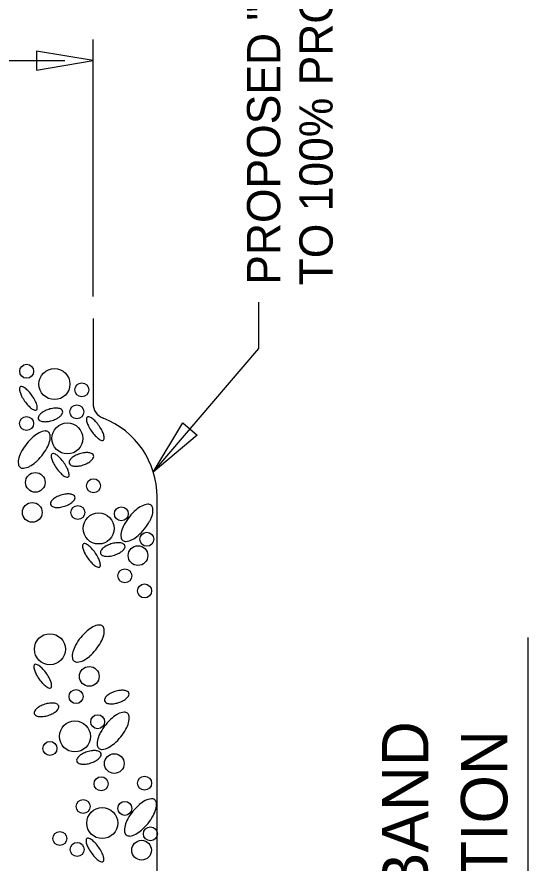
# Model space of a CAD drawing. Extents: x 0 to 8.5, y 0 to 11.
# Drawn here: x 5.35 to 6.273, y 8.342 to 9.87 of the extents above; entities that cross this region are included whole.
import ezdxf

# ---------------------------------------------------------------- set-up
doc = ezdxf.new("R2010")
doc.units = 0
for name, color, linetype in [('DTL-GRAVEL', 7, 'Continuous'), ('DTL-TEXT', 7, 'Continuous'), ('Old_Level_11', 7, 'Continuous')]:
    doc.layers.add(name, color=color, linetype=linetype)

msp = doc.modelspace()

# ---------------------------------------------------------------- linework, layer by layer
at = {"layer": 'DTL-GRAVEL'}
for centre, radius in [((5.3671, 9.2304), 0.0126), ((5.4174, 9.2073), 0.028), ((5.4669, 9.1968), 0.0126), ((5.4579, 9.1571), 0.0126), ((5.367, 9.1361), 0.0126), ((5.4407, 9.1092), 0.028), ((5.3828, 9.0298), 0.0178), ((5.4878, 9.0237), 0.0126), ((5.3773, 8.9756), 0.0178), ((5.4596, 8.9753), 0.0126), ((5.4972, 8.9465), 0.028), ((5.5382, 8.973), 0.0126), ((5.5844, 8.927), 0.0126), ((5.5683, 8.8975), 0.0178), ((5.5444, 8.861), 0.0126), ((5.5802, 8.8337), 0.0126), ((5.4092, 8.7284), 0.028), ((5.4803, 8.6794), 0.0178), ((5.4564, 8.6429), 0.0126), ((5.4954, 8.5975), 0.0126), ((5.4544, 8.5709), 0.028), ((5.4092, 8.5493), 0.0126), ((5.5255, 8.522), 0.0178), ((5.5016, 8.4855), 0.0126), ((5.5802, 8.4865), 0.0126), ((5.4692, 8.4443), 0.0126), ((5.5446, 8.441), 0.0126), ((5.5036, 8.4145), 0.028), ((5.5907, 8.395), 0.0126), ((5.4272, 8.3866), 0.0126), ((5.4585, 8.3669), 0.0126), ((5.5747, 8.3655), 0.0178)]:
    msp.add_circle(centre, radius, dxfattribs=at)
for centre, radius, start, end in [((5.3744, 9.1988), 0.0203, 176.964, 197.0838), ((5.3574, 9.1997), 0.00323, 125.0965, 176.964), ((5.3574, 9.1997), 0.00323, 73.2289, 125.0965), ((5.3525, 9.1834), 0.0203, 53.1091, 73.2289), ((5.3964, 9.2056), 0.0432, 197.0838, 207.4256), ((5.4277, 9.2218), 0.0785, 207.4256, 215.0965), ((5.3387, 9.1651), 0.0432, 42.7673, 53.1091), ((5.3128, 9.1411), 0.0785, 35.0965, 42.7673), ((5.3128, 9.1411), 0.0785, 27.4256, 35.0965), ((5.4277, 9.2218), 0.0785, 215.0965, 222.7673), ((5.3441, 9.1574), 0.0432, 17.0838, 27.4256), ((5.366, 9.1641), 0.0203, 356.964, 17.0838), ((5.4018, 9.1979), 0.0432, 222.7673, 233.1091), ((5.388, 9.1795), 0.0203, 233.1091, 253.2289), ((5.3831, 9.1632), 0.00323, 253.2289, 305.0965), ((5.3831, 9.1632), 0.00323, 305.0965, 356.964), ((5.4127, 9.1313), 0.0304, 118.2722, 132.0822), ((5.4223, 9.1134), 0.0506, 107.5826, 118.2722), ((5.4223, 9.1134), 0.0506, 96.893, 107.5826), ((5.4198, 9.1335), 0.0304, 83.0831, 96.893), ((5.4215, 9.1471), 0.0167, 59.8512, 83.0831), ((5.4168, 9.1618), 0.0167, 312.0822, 335.3141), ((5.4272, 9.1571), 0.0052, 17.5826, 59.8512), ((5.4272, 9.1571), 0.0052, 335.3141, 17.5826), ((5.3931, 9.1462), 0.0052, 155.3141, 197.5826), ((5.3931, 9.1462), 0.0052, 197.5826, 239.8512), ((5.4035, 9.1414), 0.0167, 132.0822, 155.3141), ((5.3988, 9.1561), 0.0167, 239.8512, 263.0831), ((5.4005, 9.1698), 0.0304, 263.0831, 276.893), ((5.398, 9.1898), 0.0506, 276.893, 287.5826), ((5.398, 9.1898), 0.0506, 287.5826, 298.2722), ((5.4076, 9.172), 0.0304, 298.2722, 312.0822), ((5.4784, 9.1452), 0.00323, 125.0965, 176.964), ((5.4954, 9.1443), 0.0203, 176.964, 197.0838), ((5.4784, 9.1452), 0.00323, 73.2289, 125.0965), ((5.4735, 9.1289), 0.0203, 53.1091, 73.2289), ((5.4597, 9.1105), 0.0432, 42.7673, 53.1091), ((5.4338, 9.0866), 0.0785, 35.0965, 42.7673), ((5.5173, 9.151), 0.0432, 197.0838, 207.4256), ((5.5486, 9.1673), 0.0785, 207.4256, 215.0965), ((5.4338, 9.0866), 0.0785, 27.4256, 35.0965), ((5.4412, 9.0401), 0.0951, 130.9175, 140.9829), ((5.4156, 9.0697), 0.056, 117.7861, 130.9175), ((5.4033, 9.093), 0.0297, 95.0094, 117.7861), ((5.4014, 9.1143), 0.00824, 50.9829, 95.0094), ((5.4014, 9.1143), 0.00824, 6.9564, 50.9829), ((5.3801, 9.1117), 0.0297, 344.1797, 6.9564), ((5.5486, 9.1673), 0.0785, 215.0965, 222.7673), ((5.5228, 9.1433), 0.0432, 222.7673, 233.1091), ((5.509, 9.125), 0.0203, 233.1091, 253.2289), ((5.4651, 9.1028), 0.0432, 17.0838, 27.4256), ((5.504, 9.1087), 0.00323, 305.0965, 356.964), ((5.487, 9.1096), 0.0203, 356.964, 17.0838), ((5.4412, 9.0401), 0.0951, 140.9829, 151.0483), ((5.3548, 9.1189), 0.056, 331.0483, 344.1797), ((5.504, 9.1087), 0.00323, 253.2289, 305.0965), ((5.4069, 9.0591), 0.056, 151.0483, 164.1797), ((5.3206, 9.1378), 0.0951, 310.9175, 320.9829), ((5.3206, 9.1378), 0.0951, 320.9829, 331.0483), ((5.4318, 9.0779), 0.0203, 176.964, 197.0838), ((5.4148, 9.0788), 0.00323, 125.0965, 176.964), ((5.4148, 9.0788), 0.00323, 73.2289, 125.0965), ((5.4099, 9.0624), 0.0203, 53.1091, 73.2289), ((5.3961, 9.0441), 0.0432, 42.7673, 53.1091), ((5.4685, 9.0508), 0.0304, 118.2722, 132.0822), ((5.4781, 9.033), 0.0506, 107.5826, 118.2722), ((5.4781, 9.033), 0.0506, 96.893, 107.5826), ((5.4757, 9.0531), 0.0304, 83.0831, 96.893), ((5.4773, 9.0667), 0.0167, 59.8512, 83.0831), ((5.4831, 9.0766), 0.0052, 17.5826, 59.8512), ((5.4831, 9.0766), 0.0052, 335.3141, 17.5826), ((5.3816, 9.0662), 0.0297, 164.1797, 186.9564), ((5.3604, 9.0636), 0.00824, 186.9564, 230.9829), ((5.3462, 9.1083), 0.056, 297.7861, 310.9175), ((5.4538, 9.0846), 0.0432, 197.0838, 207.4256), ((5.4851, 9.1008), 0.0785, 207.4256, 215.0965), ((5.3702, 9.0201), 0.0785, 35.0965, 42.7673), ((5.3702, 9.0201), 0.0785, 27.4256, 35.0965), ((5.4489, 9.0658), 0.0052, 155.3141, 197.5826), ((5.4489, 9.0658), 0.0052, 197.5826, 239.8512), ((5.4593, 9.061), 0.0167, 132.0822, 155.3141), ((5.4539, 9.1094), 0.0506, 287.5826, 298.2722), ((5.4635, 9.0916), 0.0304, 298.2722, 312.0822), ((5.4726, 9.0814), 0.0167, 312.0822, 335.3141), ((5.3604, 9.0636), 0.00824, 230.9829, 275.0094), ((5.3585, 9.085), 0.0297, 275.0094, 297.7861), ((5.4851, 9.1008), 0.0785, 215.0965, 222.7673), ((5.4592, 9.0769), 0.0432, 222.7673, 233.1091), ((5.4015, 9.0364), 0.0432, 17.0838, 27.4256), ((5.4234, 9.0431), 0.0203, 356.964, 17.0838), ((5.4546, 9.0757), 0.0167, 239.8512, 263.0831), ((5.4563, 9.0893), 0.0304, 263.0831, 276.893), ((5.4539, 9.1094), 0.0506, 276.893, 287.5826), ((5.4454, 9.0585), 0.0203, 233.1091, 253.2289), ((5.4405, 9.0422), 0.00323, 253.2289, 305.0965), ((5.4405, 9.0422), 0.00323, 305.0965, 356.964), ((5.4348, 8.9763), 0.0304, 118.2722, 132.0822), ((5.4444, 8.9585), 0.0506, 107.5826, 118.2722), ((5.4444, 8.9585), 0.0506, 96.893, 107.5826), ((5.4419, 8.9786), 0.0304, 83.0831, 96.893), ((5.4436, 8.9922), 0.0167, 59.8512, 83.0831), ((5.4493, 9.0021), 0.0052, 17.5826, 59.8512), ((5.4493, 9.0021), 0.0052, 335.3141, 17.5826), ((5.4152, 8.9913), 0.0052, 155.3141, 197.5826), ((5.4152, 8.9913), 0.0052, 197.5826, 239.8512), ((5.4256, 8.9865), 0.0167, 132.0822, 155.3141), ((5.4209, 9.0012), 0.0167, 239.8512, 263.0831), ((5.4202, 9.0349), 0.0506, 276.893, 287.5826), ((5.4202, 9.0349), 0.0506, 287.5826, 298.2722), ((5.4297, 9.0171), 0.0304, 298.2722, 312.0822), ((5.4389, 9.0069), 0.0167, 312.0822, 335.3141), ((5.6011, 8.9374), 0.056, 117.7861, 130.9175), ((5.5888, 8.9607), 0.0297, 95.0094, 117.7861), ((5.5869, 8.9821), 0.00824, 50.9829, 95.0094), ((5.5869, 8.9821), 0.00824, 6.9564, 50.9829), ((5.4226, 9.0148), 0.0304, 263.0831, 276.893), ((5.6267, 8.9079), 0.0951, 130.9175, 140.9829), ((5.5404, 8.9866), 0.056, 331.0483, 344.1797), ((5.5657, 8.9795), 0.0297, 344.1797, 6.9564), ((5.6267, 8.9079), 0.0951, 140.9829, 151.0483), ((5.5061, 9.0056), 0.0951, 320.9829, 331.0483), ((5.5672, 8.934), 0.0297, 164.1797, 186.9564), ((5.5925, 8.9268), 0.056, 151.0483, 164.1797), ((5.5061, 9.0056), 0.0951, 310.9175, 320.9829), ((5.5459, 8.9314), 0.00824, 186.9564, 230.9829), ((5.5459, 8.9314), 0.00824, 230.9829, 275.0094), ((5.544, 8.9527), 0.0297, 275.0094, 297.7861), ((5.5317, 8.976), 0.056, 297.7861, 310.9175), ((5.4714, 8.9161), 0.00323, 125.0965, 176.964), ((5.4884, 8.9152), 0.0203, 176.964, 197.0838), ((5.4714, 8.9161), 0.00323, 73.2289, 125.0965), ((5.4665, 8.8997), 0.0203, 53.1091, 73.2289), ((5.4527, 8.8814), 0.0432, 42.7673, 53.1091), ((5.4268, 8.8574), 0.0785, 35.0965, 42.7673), ((5.5159, 8.8983), 0.0167, 132.0822, 155.3141), ((5.5251, 8.8881), 0.0304, 118.2722, 132.0822), ((5.5347, 8.8703), 0.0506, 107.5826, 118.2722), ((5.5347, 8.8703), 0.0506, 96.893, 107.5826), ((5.5322, 8.8904), 0.0304, 83.0831, 96.893), ((5.5339, 8.904), 0.0167, 59.8512, 83.0831), ((5.5292, 8.9187), 0.0167, 312.0822, 335.3141), ((5.5397, 8.9139), 0.0052, 17.5826, 59.8512), ((5.5397, 8.9139), 0.0052, 335.3141, 17.5826), ((5.5103, 8.9219), 0.0432, 197.0838, 207.4256), ((5.5416, 8.9381), 0.0785, 207.4256, 215.0965), ((5.4268, 8.8574), 0.0785, 27.4256, 35.0965), ((5.5055, 8.9031), 0.0052, 155.3141, 197.5826), ((5.5055, 8.9031), 0.0052, 197.5826, 239.8512), ((5.5112, 8.913), 0.0167, 239.8512, 263.0831), ((5.5129, 8.9266), 0.0304, 263.0831, 276.893), ((5.5105, 8.9467), 0.0506, 276.893, 287.5826), ((5.5105, 8.9467), 0.0506, 287.5826, 298.2722), ((5.52, 8.9289), 0.0304, 298.2722, 312.0822), ((5.5416, 8.9381), 0.0785, 215.0965, 222.7673), ((5.5158, 8.9142), 0.0432, 222.7673, 233.1091), ((5.502, 8.8958), 0.0203, 233.1091, 253.2289), ((5.4581, 8.8737), 0.0432, 17.0838, 27.4256), ((5.497, 8.8795), 0.00323, 305.0965, 356.964), ((5.48, 8.8804), 0.0203, 356.964, 17.0838), ((5.497, 8.8795), 0.00323, 253.2289, 305.0965), ((5.5008, 8.7426), 0.0297, 95.0094, 117.7861), ((5.499, 8.7639), 0.00824, 50.9829, 95.0094), ((5.5387, 8.6898), 0.0951, 130.9175, 140.9829), ((5.5131, 8.7193), 0.056, 117.7861, 130.9175), ((5.499, 8.7639), 0.00824, 6.9564, 50.9829), ((5.4777, 8.7614), 0.0297, 344.1797, 6.9564), ((5.5387, 8.6898), 0.0951, 140.9829, 151.0483), ((5.4181, 8.7875), 0.0951, 320.9829, 331.0483), ((5.4524, 8.7685), 0.056, 331.0483, 344.1797), ((5.5045, 8.7087), 0.056, 151.0483, 164.1797), ((5.4181, 8.7875), 0.0951, 310.9175, 320.9829), ((5.4792, 8.7159), 0.0297, 164.1797, 186.9564), ((5.4579, 8.7133), 0.00824, 186.9564, 230.9829), ((5.4438, 8.7579), 0.056, 297.7861, 310.9175), ((5.4004, 8.6971), 0.0203, 176.964, 197.0838), ((5.3834, 8.698), 0.00323, 125.0965, 176.964), ((5.3834, 8.698), 0.00323, 73.2289, 125.0965), ((5.3785, 8.6816), 0.0203, 53.1091, 73.2289), ((5.3647, 8.6633), 0.0432, 42.7673, 53.1091), ((5.4579, 8.7133), 0.00824, 230.9829, 275.0094), ((5.456, 8.7346), 0.0297, 275.0094, 297.7861), ((5.4224, 8.7038), 0.0432, 197.0838, 207.4256), ((5.4536, 8.72), 0.0785, 207.4256, 215.0965), ((5.3388, 8.6393), 0.0785, 35.0965, 42.7673), ((5.3388, 8.6393), 0.0785, 27.4256, 35.0965), ((5.4536, 8.72), 0.0785, 215.0965, 222.7673), ((5.4278, 8.6961), 0.0432, 222.7673, 233.1091), ((5.3701, 8.6556), 0.0432, 17.0838, 27.4256), ((5.392, 8.6623), 0.0203, 356.964, 17.0838), ((5.414, 8.6777), 0.0203, 233.1091, 253.2289), ((5.4091, 8.6614), 0.00323, 253.2289, 305.0965), ((5.4091, 8.6614), 0.00323, 305.0965, 356.964), ((5.542, 8.6038), 0.0506, 107.5826, 118.2722), ((5.542, 8.6038), 0.0506, 96.893, 107.5826), ((5.5396, 8.6239), 0.0304, 83.0831, 96.893), ((5.5413, 8.6375), 0.0167, 59.8512, 83.0831), ((5.547, 8.6475), 0.0052, 17.5826, 59.8512), ((5.5128, 8.6366), 0.0052, 155.3141, 197.5826), ((5.5128, 8.6366), 0.0052, 197.5826, 239.8512), ((5.5233, 8.6318), 0.0167, 132.0822, 155.3141), ((5.5325, 8.6217), 0.0304, 118.2722, 132.0822), ((5.5178, 8.6802), 0.0506, 287.5826, 298.2722), ((5.5274, 8.6624), 0.0304, 298.2722, 312.0822), ((5.5366, 8.6522), 0.0167, 312.0822, 335.3141), ((5.547, 8.6475), 0.0052, 335.3141, 17.5826), ((5.3964, 8.6088), 0.0167, 132.0822, 155.3141), ((5.4056, 8.5986), 0.0304, 118.2722, 132.0822), ((5.4151, 8.5808), 0.0506, 107.5826, 118.2722), ((5.4151, 8.5808), 0.0506, 96.893, 107.5826), ((5.4127, 8.6009), 0.0304, 83.0831, 96.893), ((5.4144, 8.6145), 0.0167, 59.8512, 83.0831), ((5.4097, 8.6292), 0.0167, 312.0822, 335.3141), ((5.4201, 8.6244), 0.0052, 17.5826, 59.8512), ((5.4201, 8.6244), 0.0052, 335.3141, 17.5826), ((5.5186, 8.6465), 0.0167, 239.8512, 263.0831), ((5.5203, 8.6602), 0.0304, 263.0831, 276.893), ((5.5178, 8.6802), 0.0506, 276.893, 287.5826), ((5.3859, 8.6136), 0.0052, 155.3141, 197.5826), ((5.3859, 8.6136), 0.0052, 197.5826, 239.8512), ((5.3917, 8.6235), 0.0167, 239.8512, 263.0831), ((5.3933, 8.6371), 0.0304, 263.0831, 276.893), ((5.3909, 8.6572), 0.0506, 276.893, 287.5826), ((5.3909, 8.6572), 0.0506, 287.5826, 298.2722), ((5.4005, 8.6394), 0.0304, 298.2722, 312.0822), ((5.5839, 8.5323), 0.0951, 130.9175, 140.9829), ((5.5582, 8.5619), 0.056, 117.7861, 130.9175), ((5.546, 8.5852), 0.0297, 95.0094, 117.7861), ((5.5441, 8.6065), 0.00824, 50.9829, 95.0094), ((5.5441, 8.6065), 0.00824, 6.9564, 50.9829), ((5.5228, 8.6039), 0.0297, 344.1797, 6.9564), ((5.5839, 8.5323), 0.0951, 140.9829, 151.0483), ((5.4975, 8.6111), 0.056, 331.0483, 344.1797), ((5.5496, 8.5513), 0.056, 151.0483, 164.1797), ((5.4633, 8.63), 0.0951, 320.9829, 331.0483), ((5.5243, 8.5584), 0.0297, 164.1797, 186.9564), ((5.4889, 8.6005), 0.056, 297.7861, 310.9175), ((5.4633, 8.63), 0.0951, 310.9175, 320.9829), ((5.4918, 8.4948), 0.0506, 107.5826, 118.2722), ((5.4918, 8.4948), 0.0506, 96.893, 107.5826), ((5.4894, 8.5149), 0.0304, 83.0831, 96.893), ((5.4911, 8.5285), 0.0167, 59.8512, 83.0831), ((5.503, 8.5558), 0.00824, 186.9564, 230.9829), ((5.503, 8.5558), 0.00824, 230.9829, 275.0094), ((5.4968, 8.5384), 0.0052, 17.5826, 59.8512), ((5.5012, 8.5772), 0.0297, 275.0094, 297.7861), ((5.4626, 8.5276), 0.0052, 155.3141, 197.5826), ((5.4731, 8.5228), 0.0167, 132.0822, 155.3141), ((5.4822, 8.5126), 0.0304, 118.2722, 132.0822), ((5.4772, 8.5534), 0.0304, 298.2722, 312.0822), ((5.4864, 8.5432), 0.0167, 312.0822, 335.3141), ((5.4968, 8.5384), 0.0052, 335.3141, 17.5826), ((5.4626, 8.5276), 0.0052, 197.5826, 239.8512), ((5.4684, 8.5375), 0.0167, 239.8512, 263.0831), ((5.47, 8.5511), 0.0304, 263.0831, 276.893), ((5.4676, 8.5712), 0.0506, 276.893, 287.5826), ((5.4676, 8.5712), 0.0506, 287.5826, 298.2722), ((5.6074, 8.4054), 0.056, 117.7861, 130.9175), ((5.5952, 8.4287), 0.0297, 95.0094, 117.7861), ((5.5933, 8.4501), 0.00824, 50.9829, 95.0094), ((5.5933, 8.4501), 0.00824, 6.9564, 50.9829), ((5.572, 8.4475), 0.0297, 344.1797, 6.9564), ((5.6331, 8.3759), 0.0951, 140.9829, 151.0483), ((5.6331, 8.3759), 0.0951, 130.9175, 140.9829), ((5.5467, 8.4546), 0.056, 331.0483, 344.1797), ((5.5988, 8.3948), 0.056, 151.0483, 164.1797), ((5.5125, 8.4736), 0.0951, 320.9829, 331.0483), ((5.5735, 8.402), 0.0297, 164.1797, 186.9564), ((5.5125, 8.4736), 0.0951, 310.9175, 320.9829), ((5.5522, 8.3994), 0.00824, 186.9564, 230.9829), ((5.5522, 8.3994), 0.00824, 230.9829, 275.0094), ((5.5504, 8.4207), 0.0297, 275.0094, 297.7861), ((5.5381, 8.444), 0.056, 297.7861, 310.9175), ((5.4777, 8.3841), 0.00323, 125.0965, 176.964), ((5.4948, 8.3832), 0.0203, 176.964, 197.0838), ((5.5167, 8.3899), 0.0432, 197.0838, 207.4256), ((5.4777, 8.3841), 0.00323, 73.2289, 125.0965), ((5.4728, 8.3678), 0.0203, 53.1091, 73.2289), ((5.459, 8.3494), 0.0432, 42.7673, 53.1091), ((5.4332, 8.3254), 0.0785, 35.0965, 42.7673), ((5.548, 8.4062), 0.0785, 207.4256, 215.0965), ((5.548, 8.4062), 0.0785, 215.0965, 222.7673), ((5.4332, 8.3254), 0.0785, 27.4256, 35.0965), ((5.4644, 8.3417), 0.0432, 17.0838, 27.4256), ((5.5221, 8.3822), 0.0432, 222.7673, 233.1091), ((5.5083, 8.3638), 0.0203, 233.1091, 253.2289), ((5.5034, 8.3475), 0.00323, 253.2289, 305.0965), ((5.5034, 8.3475), 0.00323, 305.0965, 356.964), ((5.4864, 8.3484), 0.0203, 356.964, 17.0838)]:
    msp.add_arc(centre, radius, start, end, dxfattribs=at)
at = {"layer": 'DTL-TEXT'}
for p, q in [((5.4871, 9.3654), (5.4871, 9.8299)), ((5.2924, 9.7915), (5.4359, 9.7915)), ((5.4871, 9.326), (5.4871, 9.1725)), ((5.6028, 7.4109), (5.6028, 9.0036))]:
    msp.add_line(p, q, dxfattribs=at)
for points in [[(5.3847, 9.7744), (5.4871, 9.7915), (5.3847, 9.8085)], [(5.6755, 9.1153), (5.596, 9.0485), (5.6495, 9.1375)]]:
    msp.add_lwpolyline(points, close=True, dxfattribs=at)
msp.add_lwpolyline([(5.596, 9.0485), (5.7866, 9.2717), (5.7866, 9.3551)], dxfattribs=at)
for centre, radius, start, end in [((5.516, 9.1725), 0.0289, 180, 248.8172), ((5.4506, 9.0036), 0.1522, 0, 68.8172)]:
    msp.add_arc(centre, radius, start, end, dxfattribs=at)
at = {"layer": 'Old_Level_11'}
msp.add_line((6.2732, 7.5518), (6.2732, 8.7495), dxfattribs=at)

# ---------------------------------------------------------------- texts
at = {"layer": 'DTL-TEXT'}
for s, p in [('PROPOSED "ABC" COMPACTED', (5.8253, 9.3867)), ('TO 100% PROCTOR', (5.92, 9.3856))]:
    msp.add_text(s, height=0.06, rotation=90, dxfattribs=at).set_placement(p)
at = {"layer": 'Old_Level_11'}
for s, p in [('CONCRETE BAND', (6.093, 7.6248)), ('CROSS-SECTION', (6.2358, 7.6461))]:
    msp.add_text(s, height=0.084, rotation=90, dxfattribs=at).set_placement(p)

doc.saveas('drawing.dxf')
